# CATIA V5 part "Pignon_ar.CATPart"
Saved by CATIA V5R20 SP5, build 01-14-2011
Part number: Skl_Pignon_ar
Publications: "Plan xy", "Axe_pivot_pignon_ar/bras_ar"
Bounding box of the stored display mesh (mm): x -5 to 5, y 0 to 187.727, z 0 to 150
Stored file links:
  U:\2A\CFAO\dossier sans titre\Pignon_ar.CATPart
  U:\2A\CFAO\dossier sans titre\Skl_gouvernail.CATProduct
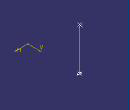
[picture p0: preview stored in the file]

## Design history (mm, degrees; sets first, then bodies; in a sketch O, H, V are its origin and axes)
Set1
  Point1 to Point3: linked copy from another document
Body1 (main body)
  Line1 "Axe_pivot_pignon_ar/bras_ar": type PtPt, FirstPoint Point1, SecondPoint Point2
  Line2: type PtPt, FirstPoint Point1, SecondPoint Point3
  Sketch1 on xy-plane, origin (0, 0, 0), H (1, 0, 0), V (0, 1, 0)
    circle A1 centre (0, 182.7273) radius 5
    point P1 (0, 182.7273)
    reference projected point E1 (0, 182.7273) from Point2
    reference projected point E2 (0, 187.7273) from Point3
    coincidence: P1 E1, A1 E2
